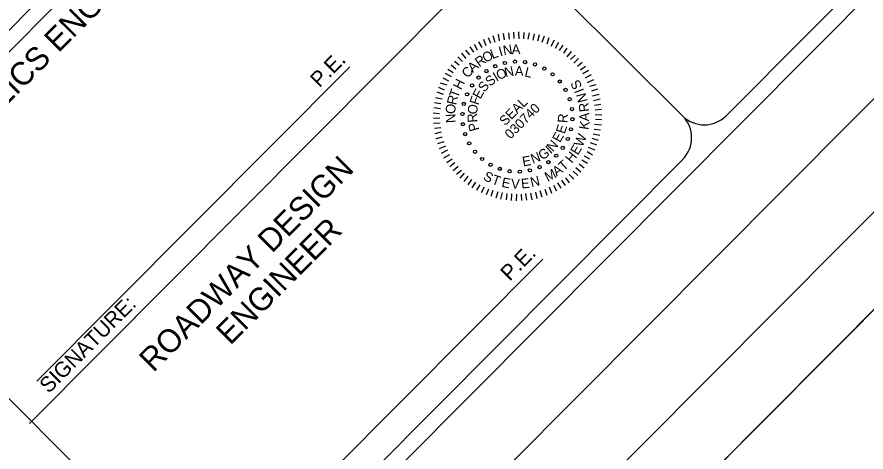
# Model space of a CAD drawing. Extents: x 1481763 to 1495577, y 493394 to 506245.
# Drawn here: x 1489667 to 1490496, y 498495 to 498920 of the extents above; entities that cross this region are included whole.
import ezdxf

# ---------------------------------------------------------------- set-up
doc = ezdxf.new("R2010")
doc.units = 0
for name, color, linetype in [('Old_Level_9', 7, 'Continuous'), ('Sheet Cutting Line CELL', 7, 'Continuous'), ('Sheet Plot Border Inside CELL', 7, 'Continuous'), ('Sheet Plot Border Outside CELL', 7, 'Continuous'), ('Sheet Title CELL', 7, 'Continuous')]:
    doc.layers.add(name, color=color, linetype=linetype)

msp = doc.modelspace()

# ---------------------------------------------------------------- linework, layer by layer
at = {"layer": 'Old_Level_9'}
for p, q in [((1490136.82, 498902.95), (1490138.07, 498896.41)), ((1490141.95, 498903.49), (1490142.84, 498897.3)), ((1490146.89, 498904.21), (1490147.61, 498897.84)), ((1490152.02, 498904.75), (1490152.39, 498898.74)), ((1490156.79, 498904.93), (1490156.98, 498898.39)), ((1490162.1, 498904.59), (1490161.58, 498898.4)), ((1490167.22, 498904.07), (1490166, 498897.88)), ((1490172, 498903.2), (1490170.77, 498897.01)), ((1490117.92, 498895.31), (1490120.94, 498889.83)), ((1490122.69, 498897.97), (1490124.82, 498891.61)), ((1490127.11, 498899.57), (1490129.59, 498893.92)), ((1490131.7, 498901.35), (1490133.83, 498894.99)), ((1490176.95, 498902.15), (1490175.37, 498895.96)), ((1490181.9, 498900.74), (1490179.62, 498894.55)), ((1490186.33, 498899.16), (1490184.57, 498893.15)), ((1490191.46, 498896.87), (1490188.29, 498890.86)), ((1490105.21, 498887.15), (1490109.11, 498882.56)), ((1490109.45, 498890.34), (1490112.82, 498885.22)), ((1490113.51, 498893), (1490116.52, 498887.53)), ((1490195.88, 498894.59), (1490192.71, 498888.92)), ((1490200.13, 498892.12), (1490196.6, 498886.81)), ((1490204.02, 498889.3), (1490200.68, 498884.17)), ((1490097.62, 498880.59), (1490102.23, 498876.01)), ((1490101.33, 498884.31), (1490105.4, 498879.2)), ((1490208.1, 498885.95), (1490204.04, 498880.81)), ((1490211.99, 498882.42), (1490207.58, 498877.99)), ((1490215.36, 498879.07), (1490210.95, 498874.64)), ((1490091.1, 498872.98), (1490095.7, 498869.1)), ((1490094.27, 498876.52), (1490099.05, 498872.82)), ((1490218.9, 498875.19), (1490214.31, 498871.29)), ((1490222.27, 498871.13), (1490217.15, 498867.76)), ((1490085.28, 498864.66), (1490090.94, 498861.49)), ((1490087.92, 498868.73), (1490093.06, 498865.38)), ((1490225.11, 498867.25), (1490219.46, 498864.05)), ((1490227.59, 498863.01), (1490221.94, 498859.81)), ((1490080.35, 498855.46), (1490086.72, 498853.35)), ((1490082.99, 498860.23), (1490088.48, 498857.24)), ((1490230.07, 498858.42), (1490223.89, 498855.4)), ((1490232.21, 498853.47), (1490226.2, 498851.69)), ((1490077.01, 498846.43), (1490083.38, 498844.32)), ((1490078.77, 498851.03), (1490084.43, 498848.57)), ((1490233.81, 498849.06), (1490227.98, 498847.1)), ((1490075.78, 498840.95), (1490082.33, 498839.73)), ((1490235.41, 498843.93), (1490229.05, 498842.5)), ((1490236.65, 498839.52), (1490230.12, 498837.91)), ((1490074.21, 498831.22), (1490080.76, 498830.35)), ((1490074.91, 498836.18), (1490081.1, 498835.3)), ((1490237.2, 498834.39), (1490231.01, 498833.14)), ((1490237.74, 498829.26), (1490231.55, 498828.72)), ((1490073.69, 498826.1), (1490079.88, 498825.58)), ((1490073.88, 498820.97), (1490080.07, 498821.16)), ((1490238.1, 498823.96), (1490231.56, 498824.13)), ((1490073.89, 498816.02), (1490080.25, 498816.39)), ((1490074.79, 498811.25), (1490080.97, 498811.79)), ((1490237.77, 498814.06), (1490231.05, 498814.75)), ((1490237.93, 498819.19), (1490231.92, 498819.53)), ((1490075.5, 498805.95), (1490081.69, 498807.55)), ((1490236.2, 498803.98), (1490229.65, 498805.21)), ((1490236.72, 498809.11), (1490230.53, 498809.98)), ((1490076.4, 498801.18), (1490082.58, 498802.78)), ((1490078, 498796.05), (1490084.36, 498798.19)), ((1490233.39, 498794.43), (1490227.2, 498796.72)), ((1490234.79, 498799.03), (1490228.78, 498801.14)), ((1490079.78, 498791.46), (1490085.78, 498793.95)), ((1490081.73, 498786.69), (1490087.73, 498789.89)), ((1490229.17, 498784.88), (1490223.86, 498788.05)), ((1490231.45, 498789.65), (1490225.26, 498792.29)), ((1490084.04, 498782.28), (1490089.69, 498785.47)), ((1490086.88, 498777.69), (1490092.17, 498781.23)), ((1490224.06, 498776.56), (1490218.75, 498780.08)), ((1490226.52, 498780.8), (1490221.21, 498783.98)), ((1490089.71, 498773.8), (1490094.65, 498777.7)), ((1490093.08, 498769.74), (1490097.84, 498774.17)), ((1490217.71, 498768.41), (1490212.75, 498772.64)), ((1490220.88, 498772.31), (1490216.1, 498776.01)), ((1490096.27, 498766.22), (1490101.03, 498770.29)), ((1490099.99, 498762.51), (1490104.04, 498767.29)), ((1490103.71, 498759.16), (1490107.76, 498764.29)), ((1490206.59, 498757.96), (1490202.87, 498762.72)), ((1490210.65, 498761.33), (1490206.22, 498766.09)), ((1490214.54, 498764.87), (1490210.11, 498769.28)), ((1490107.6, 498755.99), (1490111.31, 498761.12)), ((1490111.68, 498752.99), (1490115.02, 498758.48)), ((1490116.1, 498750.7), (1490119.27, 498756.01)), ((1490120.7, 498748.59), (1490123.69, 498754.07)), ((1490194.06, 498749.62), (1490191.22, 498755.28)), ((1490198.47, 498752.64), (1490195.1, 498757.76)), ((1490202.71, 498755.12), (1490199.16, 498760.42)), ((1490125.65, 498746.48), (1490127.76, 498752.14)), ((1490130.08, 498744.9), (1490132.01, 498750.73)), ((1490135.03, 498743.14), (1490136.96, 498749.33)), ((1490139.63, 498742.09), (1490141.21, 498748.28)), ((1490145.11, 498741.21), (1490145.8, 498747.58)), ((1490150.06, 498740.52), (1490150.23, 498747.06)), ((1490154.84, 498740.35), (1490155.18, 498746.72)), ((1490160.14, 498740.72), (1490159.59, 498746.9)), ((1490164.91, 498740.9), (1490164.01, 498747.44)), ((1490170.04, 498741.44), (1490168.96, 498747.8)), ((1490175.16, 498742.69), (1490173.56, 498748.87)), ((1490179.93, 498743.94), (1490177.97, 498750.12)), ((1490184.7, 498745.54), (1490182.74, 498751.37)), ((1490189.47, 498747.49), (1490186.98, 498753.5))]:
    msp.add_line(p, q, dxfattribs=at)
for centre in [(1490134.14, 498871.58), (1490143.55, 498874.72), (1490153.37, 498876.07), (1490163.27, 498875.59), (1490172.92, 498873.3), (1490181.98, 498869.28), (1490117.83, 498860.45), (1490125.47, 498866.78), (1490190.14, 498863.66), (1490111.48, 498852.84), (1490197.14, 498856.64), (1490106.64, 498844.18), (1490202.73, 498848.45), (1490206.72, 498839.38), (1490103.48, 498834.79), (1490208.97, 498829.72), (1490102.09, 498824.97), (1490209.41, 498819.82), (1490102.53, 498815.07), (1490104.78, 498805.42), (1490208.02, 498810), (1490108.77, 498796.34), (1490204.85, 498800.61), (1490114.36, 498788.15), (1490200.01, 498791.96), (1490121.35, 498781.13), (1490186.03, 498778.02), (1490193.67, 498784.34), (1490129.52, 498775.51), (1490138.58, 498771.49), (1490148.23, 498769.21), (1490167.95, 498770.08), (1490177.36, 498773.22), (1490158.13, 498768.73)]:
    msp.add_circle(centre, 1.58, dxfattribs=at)
at = {"layer": 'Sheet Cutting Line CELL'}
msp.add_line((1487357.65, 495475.32), (1490922.52, 499055.04), dxfattribs=at)
msp.add_lwpolyline([(1485019.38, 497803.89), (1488584.25, 501383.61), (1490922.52, 499055.04), (1487357.65, 495475.32)], close=True, dxfattribs=at)
at = {"layer": 'Sheet Plot Border Inside CELL'}
msp.add_lwpolyline([(1487337.48, 495550.45), (1490865.3, 499092.97), (1488622.45, 501326.52), (1485094.62, 497784)], close=True, dxfattribs=at)
at = {"layer": 'Sheet Plot Border Outside CELL'}
msp.add_lwpolyline([(1488481.29, 501486.15), (1484916.42, 497906.42), (1487254.69, 495577.85), (1490819.56, 499157.58)], close=True, dxfattribs=at)
at = {"layer": 'Sheet Title CELL'}
for p, q in [((1487288.78, 496526.16), (1490294.79, 499544.69)), ((1489511.58, 498736.96), (1489934.47, 499161.61)), ((1490317.02, 498823), (1489976.9, 499161.7)), ((1489679.77, 498523.32), (1490146.91, 498992.4)), ((1489686.91, 498564.44), (1489992.28, 498871.08)), ((1489851.81, 498355.8), (1489511.69, 498694.5)), ((1489881, 498382.83), (1490180.57, 498683.59))]:
    msp.add_line(p, q, dxfattribs=at)
for points in [[(1487576.27, 496007), (1490709.29, 499153.08)], [(1490359.45, 498823.09), (1490688.05, 499153.06)], [(1489894.21, 498355.91), (1490317.11, 498780.58)]]:
    msp.add_lwpolyline(points, dxfattribs=at)
for centre, start, end in [((1490338.07, 498844.38), 225.11911, 315.11911), ((1490295.73, 498801.87), 315.11911, 45.11911)]:
    msp.add_arc(centre, 30, start, end, dxfattribs=at)

# ---------------------------------------------------------------- texts
at = {"layer": 'Old_Level_9'}
for s, height, rotation, p in [('L', 9.45, 20.86453, (1490131.39, 498878.37)), ('I', 9.45, 15.92458, (1490138.99, 498881.03)), ('N', 9.45, 10.02246, (1490142.52, 498882.1)), ('A', 9.45, 2.1237, (1490150.3, 498883.18)), ('R', 9.45, 35.14018, (1490118.5, 498870.38)), ('O', 9.45, 28.20543, (1490124.51, 498874.64)), ('C', 9.45, 50.05854, (1490107.57, 498859.4)), ('A', 9.45, 43.09349, (1490112.33, 498864.89)), ('N', 9.4, 12.51165, (1490144.16, 498860.71)), ('A', 9.4, 359.0624, (1490153.17, 498862.32)), ('L', 9.4, 346.65093, (1490162.19, 498861.81)), ('S', 9.4, 38.16008, (1490128.97, 498851.49)), ('I', 9.4, 30.60069, (1490135.33, 498856.45)), ('O', 9.4, 22.99351, (1490137.44, 498857.87)), ('H', 9.45, 62.86197, (1490100.7, 498847.9)), ('S', 9.4, 49.58665, (1490123.5, 498845.65)), ('S', 9.45, 117.37651, (1490219.25, 498851.84)), ('T', 9.45, 70.55441, (1490097.71, 498839.93)), ('E', 9.4, 61.70756, (1490119.63, 498838.92)), ('I', 9.45, 111.16502, (1490221.01, 498847.61)), ('N', 9.45, 104.49119, (1490224.34, 498837.49)), ('R', 9.45, 77.29407, (1490095.95, 498833.21)), ('F', 9.4, 71.51858, (1490117.7, 498833.08)), ('SEAL', 9.398, 45.11863, (1490143.77, 498812.97)), ('O', 9.45, 85.06284, (1490094.91, 498824.73)), ('O', 9.4, 83.37044, (1490116.3, 498824.24)), ('030740', 9.398, 45.11863, (1490149.03, 498799.97)), ('R', 9.45, 96.26894, (1490225.74, 498827.42)), ('N', 9.45, 93.18528, (1490095.46, 498816.42)), ('R', 9.4, 94.86642, (1490116.85, 498816.99)), ('R', 9.4, 85.46789, (1490204.35, 498815.94)), ('A', 9.45, 88.64031, (1490225.6, 498817.82)), ('P', 9.4, 105.24227, (1490118.63, 498809.57)), ('E', 9.4, 72.27544, (1490201.9, 498804.97)), ('K', 9.45, 81.25963, (1490224.98, 498809.16)), ('E', 9.4, 60.92431, (1490197.32, 498796.48)), ('W', 9.45, 67.12438, (1490219.2, 498792.16)), ('N', 9.4, 48.24642, (1490190.27, 498787.62)), ('E', 9.45, 59.28338, (1490214.8, 498784.33)), ('N', 9.4, 21.17698, (1490170.85, 498776.27)), ('G', 9.4, 32.59987, (1490179.86, 498779.65)), ('I', 9.4, 40.74321, (1490188.15, 498785.5)), ('H', 9.45, 51.12984, (1490208.87, 498776.33)), ('E', 9.4, 9.98781, (1490161.31, 498773.77)), ('T', 9.45, 42.50521, (1490201, 498768.82)), ('M', 9.45, 27.45566, (1490185.31, 498758.69)), ('A', 9.45, 35.30079, (1490194, 498763.77)), ('S', 9.45, 333.33063, (1490121.61, 498761.27)), ('T', 9.45, 340.74301, (1490129.95, 498757.16)), ('E', 9.45, 348.94112, (1490139.76, 498753.98)), ('E', 9.45, 5.34987, (1490159.74, 498752.26)), ('N', 9.45, 13.44762, (1490169.57, 498753.52)), ('V', 9.45, 357.04842, (1490149.38, 498752.38))]:
    msp.add_text(s, height=height, rotation=rotation, dxfattribs=at).set_placement(p)
at = {"layer": 'Sheet Title CELL'}
for s, height, p in [(' HYDRAULICS ENGINEER', 22.5, (1489559.23, 498734.8)), ('P.E.', 14.998, (1489962.61, 498849.98)), ('ROADWAY DESIGN', 22.4982, (1489800.53, 498572.41)), ('ENGINEER', 22.498, (1489875.46, 498598.76)), ('P.E.', 14.998, (1490148.24, 498661.38)), ('SIGNATURE:', 14.998, (1489698.43, 498551.81))]:
    msp.add_text(s, height=height, rotation=45.11911, dxfattribs=at).set_placement(p)

doc.saveas('drawing.dxf')
